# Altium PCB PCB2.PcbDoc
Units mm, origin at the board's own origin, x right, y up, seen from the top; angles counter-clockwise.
Board outline 27.18 x 46.74 mm, 2 copper layers (Top Layer, Bottom Layer); 37 components, 26 nets, 150 pads, 36 vias.
Unrouted connection lines stored in the file: 6.
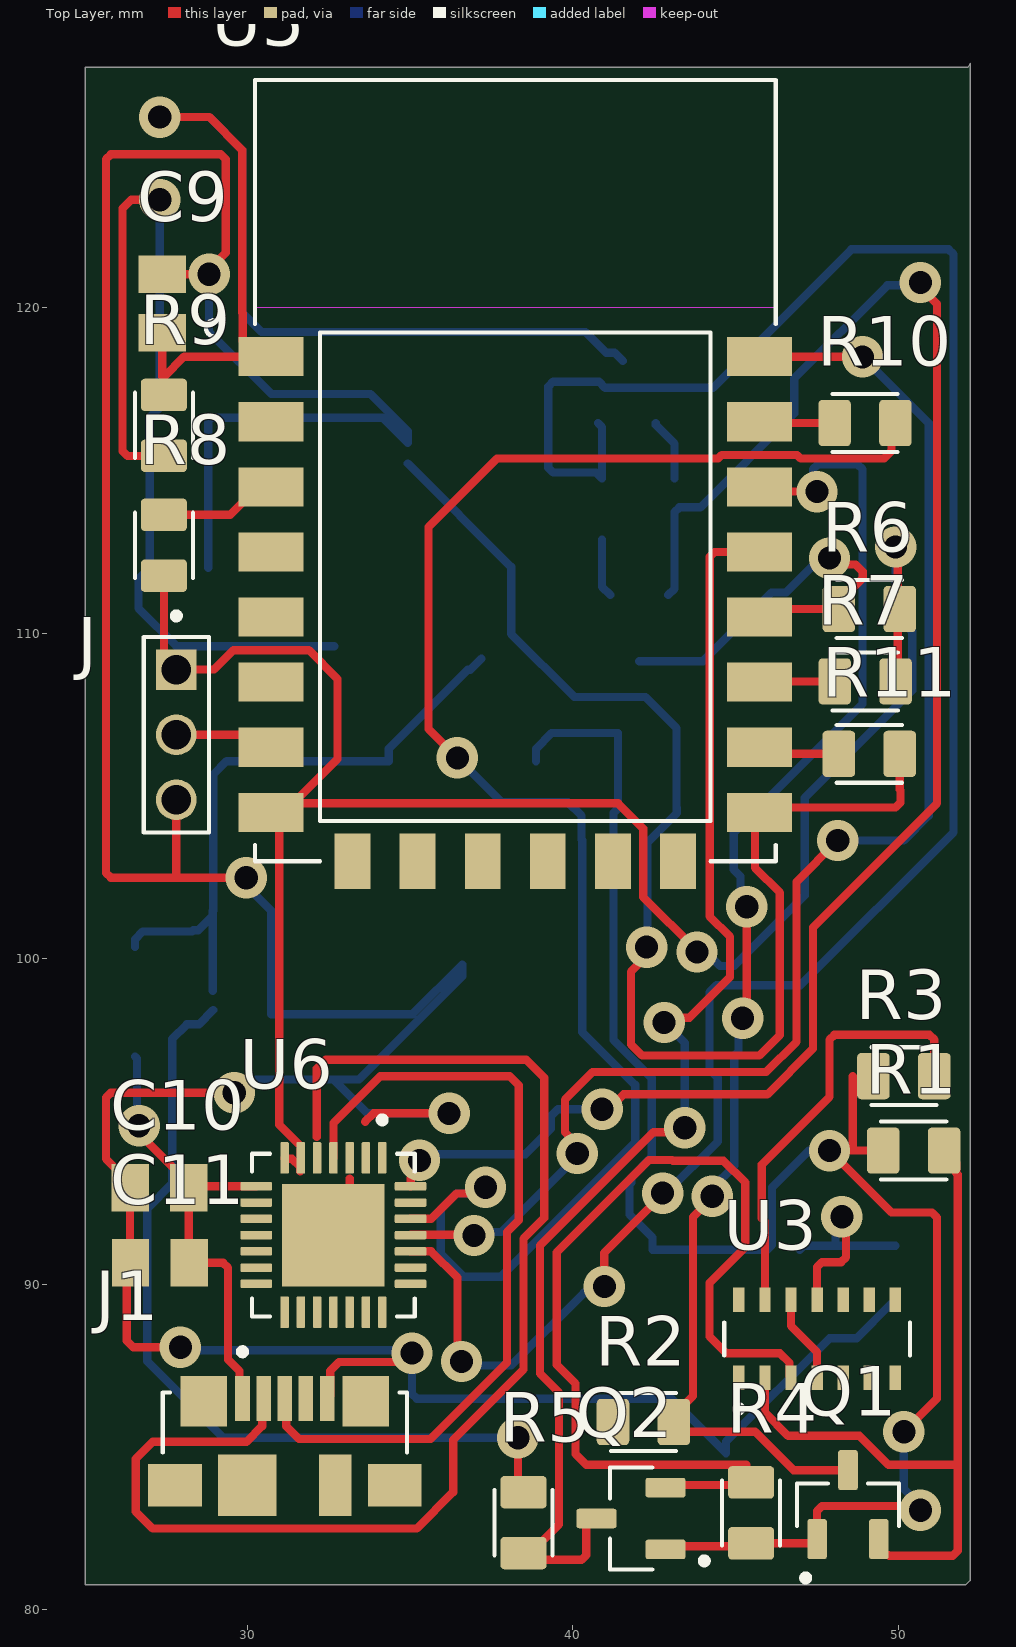
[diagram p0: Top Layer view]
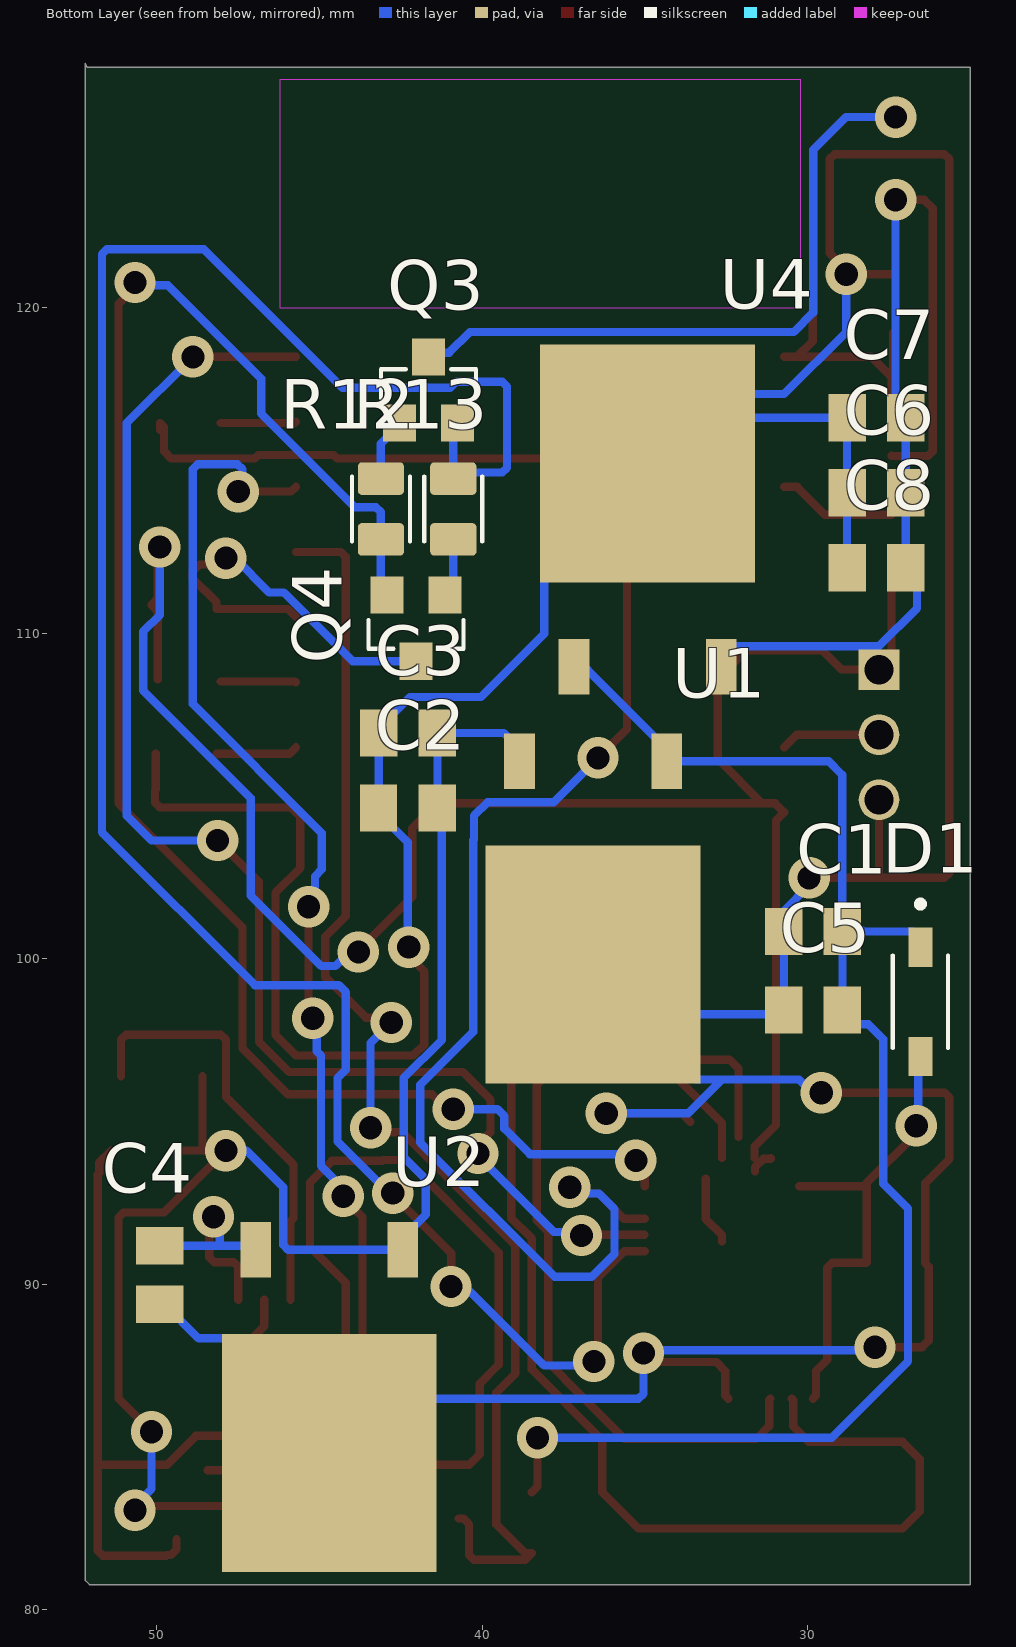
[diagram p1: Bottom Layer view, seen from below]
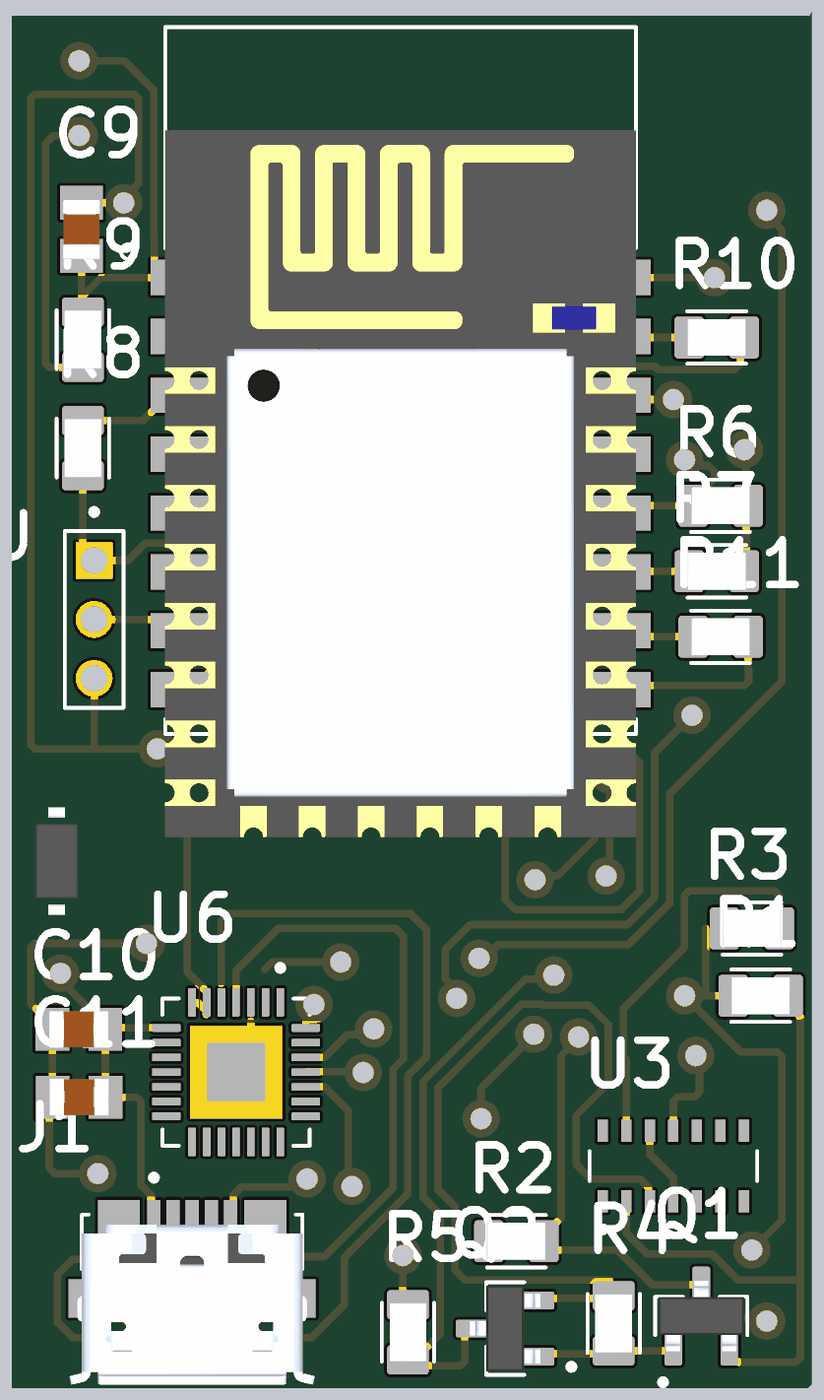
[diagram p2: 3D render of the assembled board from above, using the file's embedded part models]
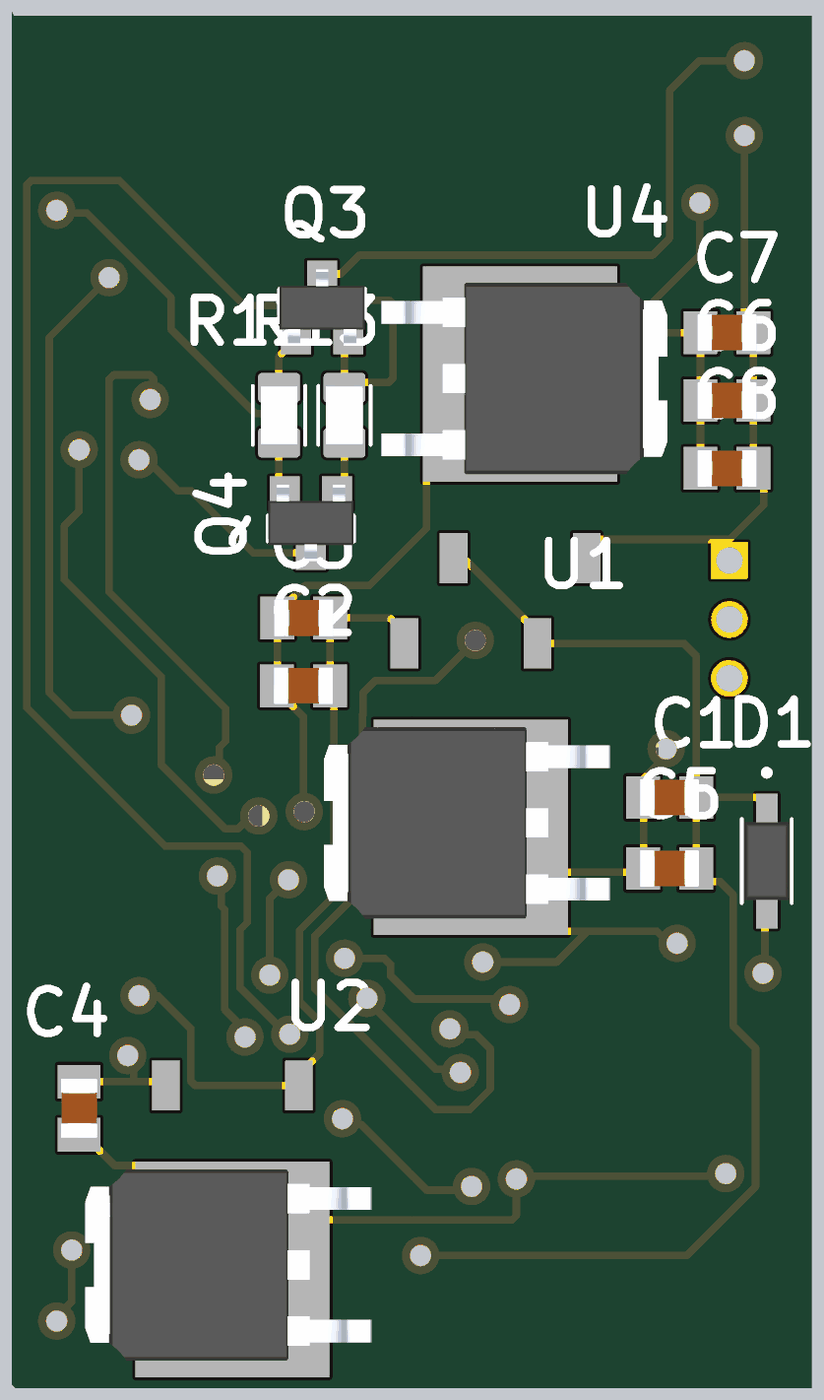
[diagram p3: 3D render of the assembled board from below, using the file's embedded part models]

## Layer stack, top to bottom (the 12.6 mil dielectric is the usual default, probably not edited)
Top Solder: solder mask 0.0102, Solder Resist, Dk 3.5
Top Layer: signal copper 0.0356
Dielectric 1: dielectric 0.32, FR-4, Dk 4.8
Bottom Layer: signal copper 0.0356
Bottom Solder: solder mask 0.0102, Solder Resist, Dk 3.5

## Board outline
25.019,80.772 25.019,127.381 52.133,127.381 52.197,127.508 52.197,80.899 52.07,80.772

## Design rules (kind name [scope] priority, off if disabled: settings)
Clearance [All] p1: gap=0.254 ignorepadtopadclearanceinfootprint=FALSE except(0: Arc-Hole Track-Hole SMDPad-Hole THPad-Hole Via-Hole Fill-Hole Poly-Hole Region-Hole Text-Hole)
HoleToHoleClearance [All] p1 off: gap=0.05 allowstackedmicrovias=TRUE
MinimumSolderMaskSliver [All] p1: minsoldermaskwidth=0.05
PolygonConnect [All] p1: connectstyle=Relief reliefconductorwidth=0.254 reliefentries=4 polygonreliefangle="90 Angle" airgapwidth=0.254
RoutingVias [All] p1: holewidth=0.711 width=1.27 viastyle="Through Hole" minholewidth=0.711 minwidth=1.27 maxholewidth=0.711 maxwidth=1.27
SilkToSilkClearance [All] p1: silktosilkclearance=0.05
SilkToSolderMaskClearance [IsPad] p1: minsilkscreentomaskgap=0.05 clearancetoexposedcopper=TRUE
SolderMaskExpansion [All] p1: expansion=0.102 istentingtop=FALSE
Width [All] p1: maxlimit=0.254 minlimit=0.254 preferedwidth=0.254
26 further rules are at their usual default settings.

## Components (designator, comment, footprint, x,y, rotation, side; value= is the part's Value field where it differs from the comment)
C1 "1uF" CAPC2012X140N 29.845,100.838 r180 bottom
C2 "47uF" CAPC2012X140N 42.291,104.63 r180 bottom
C3 "0.1uF" CAPC2012X140N 42.28,106.934 r180 bottom
C4 "1uF" CAPC2012X140N 49.911,90.286 r90 bottom
C5 "10uF" CAPC2012X140N 29.845,98.425 r180 bottom
C6 "10uF" CAPC2012X140N 27.896,114.318 r180 bottom
C7 "10uF" CAPC2012X140N 27.896,116.623 r0 bottom
C8 "100nF" CAPC2012X140N 27.896,112.014 r0 bottom
C9 "100nF" CAPC2012X140N 27.384,120.131 r270 top
C10 "100nF" CAPC2012X140N 27.294,92.964 r0 top
C11 "10uF" CAPC2012X140N 27.305,90.66 r0 top
D1 "1N5819HW-7-F" SOD3715X145N 26.543,98.679 r270 bottom
J "2355186-3" TE_2355186-3 27.813,108.883 r270 top
J1 "47346-0001" MOLEX_47346-0001 31.145,83.827 r0 top
Q1 "BSS138" SOT95P240X111-3N 48.448,83.229 r90 top
Q2 "BSS138" SOT95P240X111-3N 41.783,82.804 r180 top
Q3 "SMD-TRANSISTORS-NPN-25V-500MW(SOT-23)" SOT-23 41.656,117.475 r180 bottom
Q4 "SMD-TRANSISTORS-NPN-25V-500MW(SOT-23)" SOT-23 42.037,110.158 r0 bottom
R1 "10K" RESC2012X65N 50.465,94.107 r180 top
R2 "10K" RESC2012X65N 42.164,85.768 r180 top
R3 "10K" RESC2012X65N 50.165,96.393 r180 top
R4 "10K" RESC2012X65N 45.472,82.977 r270 top
R5 "10K" RESC2012X65N 38.481,82.677 r90 top
R6 "12K" RESC2012X65N 49.103,110.744 r0 top
R7 "10K" RESC2012X65N 48.976,108.52 r0 top
R8 "10K" RESC2012X65N 27.432,112.702 r270 top
R9 "10K" RESC2012X65N 27.432,116.387 r270 top
R10 "470" RESC2012X65N 48.971,116.459 r0 top
R11 "10K" RESC2012X65N 49.103,106.295 r0 top
R12 "12K" RESC2012X65N 43.118,113.817 r90 bottom
R13 "12K" RESC2012X65N 40.894,113.817 r270 bottom
U1 "LF33CDT-TR" TO228P972X240-3N 36.599,99.974 r0 bottom
U2 "LF33CDT-TR" TO228P972X240-3N 44.704,84.963 r0 bottom
U3 "MAX30102EFD+T" XDCR_MAX30101EFD+ 47.498,88.322 r90 top
U4 "LF33CDT-TR" TO228P972X240-3N 34.925,115.062 r180 bottom
U5 "ESP8266-12E/ESP-12E" XCVR_ESP8266-12E/ESP-12E 38.227,111.497 r0 top
U6 "CP2102" QFN50P500X500X100-29N 32.639,91.511 r270 top

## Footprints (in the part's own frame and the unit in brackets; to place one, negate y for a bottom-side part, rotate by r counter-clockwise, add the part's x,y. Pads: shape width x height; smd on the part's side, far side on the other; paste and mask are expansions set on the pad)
CAPC2012X140N [mm]
  rect 1.15x1.45 smd: 1(-0.9,0) 2(0.9,0)
  body extent -1,-0.63 1,0.63, height 0.94
MOLEX_47346-0001 [mm]
  rect 0.45x1.38 smd: 1(-1.3,2.66) 2(-0.65,2.66) 3(0,2.66) 4(0.65,2.66) 5(1.3,2.66)
  rect 1.425x1.55 smd: S1(-2.488,2.575) S2(2.488,2.575)
  rect 1.65x1.3 smd: S3(-3.375,0) S6(3.375,0)
  rect 1.8x1.9 smd: S4(-1.15,0)
  rect 1x1.9 smd: S5(1.55,0)
  silkscreen extent -3.75,1 3.75,4.2, body extent -4.18,-2.93 4.18,2.5, height 2.7
QFN50P500X500X100-29N [mm]
  rrect25% 0.97x0.26 smd: 1(-2.37,1.5) 2(-2.37,1) 3(-2.37,0.5) 4(-2.37,0) 5(-2.37,-0.5) 6(-2.37,-1) 7(-2.37,-1.5) 15(2.37,-1.5) 16(2.37,-1) 17(2.37,-0.5) 18(2.37,0) 19(2.37,0.5) 20(2.37,1) 21(2.37,1.5)
  rrect25% 0.26x0.97 smd: 8(-1.5,-2.37) 9(-1,-2.37) 10(-0.5,-2.37) 11(0,-2.37) 12(0.5,-2.37) 13(1,-2.37) 14(1.5,-2.37) 22(1.5,2.37) 23(1,2.37) 24(0.5,2.37) 25(0,2.37) 26(-0.5,2.37) 27(-1,2.37) 28(-1.5,2.37)
  rect 3.15x3.15 smd paste-0.575: 29(0,0)
  silkscreen extent -3.64,-2.5 2.5,2.5
RESC2012X65N [mm]
  rrect25% 1x1.42 smd: 1(-0.935,0) 2(0.935,0)
  silkscreen extent -1,-0.89 1,0.89, body extent -1,-0.63 1,0.63, height 0.6
SOD3715X145N [mm]
  rect 1.21x0.73 smd: A(1.68,0) C(-1.68,0)
  silkscreen extent -3.1,-0.85 1.42,0.85, body extent -1.83,-0.77 1.83,0.77, height 0.8
SOT95P240X111-3N [mm]
  rrect25% 1.23x0.6 smd: 1(-1.06,0.95) 2(-1.06,-0.95) 3(1.06,0)
  silkscreen extent -2.35,-1.57 0.65,1.57, body extent -1.2,-1.46 1.2,1.46, height 1.2
SOT-23 [mil]
  rect 40x45 smd: 1(-35,-40) 2(35,-40) 3(0,40)
  silkscreen extent -58,-10 58,25, body extent -57,-51 57,51, height 55
TE_2355186-3 [mm]
  rect 1.25x1.25 hole 0.9: 1(0,0)
  round 1.25 hole 0.9: 2(2,0) 3(4,0)
  silkscreen extent -1.75,-1 5,1
TO228P972X240-3N [mil]
  rect 37x67 smd: 1(-89,-240) 3(89,-240)
  rect 260x288 smd: 2(0,6)
  body extent -186,-128 197,128, height 94
XCVR_ESP8266-12E/ESP-12E [mm]
  rect 2x1.2 smd: 1(-7.5,7) 2(-7.5,5) 3(-7.5,3) 4(-7.5,1) 5(-7.5,-1) 6(-7.5,-3) 7(-7.5,-5) 8(-7.5,-7) 15(7.5,-7) 16(7.5,-5) 17(7.5,-3) 18(7.5,-1) 19(7.5,1) 20(7.5,3) 21(7.5,5) 22(7.5,7)
  rect 1.1x1.7 smd: 9(-5,-8.5) 10(-3,-8.5) 11(-1,-8.5) 12(1,-8.5) 13(3,-8.5) 14(5,-8.5)
  Keep-Out Layer region: 8,8.51 -8.009,8.51 -8.009,15.5 8,15.5
  Keep-Out Layer region: 8,8.51 -8.009,8.51 -8.009,15.5 8,15.5
  silkscreen extent -9.5,-8.5 8,15.5, body extent -8,-12 8,12, height 3
XDCR_MAX30101EFD+ [mm]
  rect 0.75x0.35 smd: 1(-1.2,2.4) 2(-1.2,1.6) 3(-1.2,0.8) 4(-1.2,0) 5(-1.2,-0.8) 6(-1.2,-1.6) 7(-1.2,-2.4) 8(1.2,-2.4) 9(1.2,-1.6) 10(1.2,-0.8) 11(1.2,0) 12(1.2,0.8) 13(1.2,1.6) 14(1.2,2.4)
  silkscreen extent -2.25,-2.85 0.51,2.85

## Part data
C1 C2 C3 C4 C5 C6 C7 C8 C9 C10 C11: library part LD051C121KAB2A, "Ceramic Capacitor", Package="0805 AVX"
D1: "Diode Schottky 40 V 1A Surface Mount SOD-123", Package="SOD-123 Fairchild Semiconductor"
J: "Pin 3P,2MM,BRK HDR,SRVT,2.8,0.76AU,BOX 3 POS", Package=None
J1: "USB - micro B USB 2.0 Receptacle Connector 5 Position Surface Mount, Right Angle", Package=None
Q1 Q2: "N-Channel 50 V 220mA (Ta) 350mW (Ta) Surface Mount SOT-23-3", Package="SOT-23-3 Motorola"
Q3 Q4: "Bipolar (BJT) Transistor NPN 25 V 500 mA 150MHz 300 mW Surface Mount SOT-23", Package=None
R1 R2 R3 R4 R5 R6 R7 R8 R9 R10 R11 R12 R13: library part 2-2176053-0, "RES 0.33 OHM 1% 1/4W 0805", Package=0805, Power_Rating=".25 W", Resistance=.33, Tolerance=1%
U1 U2 U4: "Linear Voltage Regulator IC Positive Fixed 1 Output 500mA DPAK", Package="TO-252-3 STMicroelectronics"
U3: "Pulse Oximeter and Heart Rate Sensor Digital Output", Package=None
U5: "This WiFi module has a 32-bit MCU micro and clock speeds supporting 80 MHz or 160 MHz. Supports the RTOS and integrated Wi-Fi MAC/BB/RF/PA/LNA, and has an on-board antenna.", Package=None
U6: "CP2102N USB 2.0 to UART (RS232) Bridge Interface Evaluation Board", Package="WFQFN-20 Silicon Labs"

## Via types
v1: diameter 1.27, hole 0.711, Top Layer to Bottom Layer, tented both sides, 36 vias

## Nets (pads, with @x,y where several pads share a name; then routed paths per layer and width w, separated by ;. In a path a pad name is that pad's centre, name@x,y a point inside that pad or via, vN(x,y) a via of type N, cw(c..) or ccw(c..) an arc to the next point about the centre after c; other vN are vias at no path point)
1V8: C4.2 U2.3 U3.11 | length 7.3
  Top Layer w0.254: U3.11 47.498,90.529 47.647,90.678 48.238,90.678 48.387,90.827 48.387,91.948 v1(48.26,92.075)
  Bottom Layer w0.254: U2.3 47.092,91.186 48.006,91.186 ; v1(48.26,92.075) 48.066,91.881 48.066,91.246 48.006,91.186 ; C4.2 48.006,91.186
3V3: C2.2 C3.2 Q1.1 Q2.1 R1.2 R3.2 R4.2 U1.3 U2.1 | length 54.5
  Top Layer w0.254: Q2.1 42.937,81.948 45.378,81.948 R4.2 47.371,82.042 Q1.1 47.498,83.036 47.647,83.185 50.546,83.185 v1(50.673,83.058) ; 48.595,96.393 48.595,94.107 ; R1.2 48.595,94.107 ; v1(50.165,85.471) 51.181,86.487 51.181,92.053 51.032,92.202 49.784,92.202 v1(47.879,94.107) 48.595,94.107
  Bottom Layer w0.254: U1.3 38.86,106.451 39.342,106.934 C3.2 41.38,104.641 C2.2 41.246,104.485 41.246,97.508 42.418,96.336 42.418,93.907 41.791,93.281 41.791,93.121 41.739,93.069 41.739,92.144 42.443,91.44 U2.1 45.965,91.059 46.114,91.208 46.114,92.977 47.244,94.107 v1(47.879,94.107) ; v1(50.165,85.471) 50.165,83.715 50.673,83.207 v1(50.673,83.058)
3V3_ESP: C6.2 C7.1 C8.1 J.1 R6.2 R7.2 R8.2 R9.2 U4.3 U5.8 U6.6 U6.7 | length 91.4
  Top Layer w0.254: v1(27.305,123.317) 26.426,123.317 26.162,123.053 26.162,115.592 26.311,115.443 27.423,115.443 R9.2 ; R8.2 27.432,109.264 J.1 28.974,108.883 29.569,109.478 31.885,109.478 32.766,108.597 32.766,106.136 U5.8@31.405,104.775 ; U6.7 31.139,93.856 31.142,93.853 31.369,93.853 31.623,93.599 U6.6@31.623,93.467 ; U6.6 31.639,94.236 30.977,94.898 30.977,104.247 U5.8 31.005,104.775 U5.8@31.405,104.775 ; v1(43.808,100.21) 43.808,100.248 42.158,101.898 42.158,104.005 41.388,104.775 U5.8@31.405,104.775 ; v1(49.911,112.649) 49.974,112.585 49.974,111.061 50.165,110.871 49.974,110.68 R7.2@49.974,108.583
  Bottom Layer w0.254: v1(27.305,123.317) 27.305,116.932 C7.1 C6.2 C8.1 26.648,111.666 26.648,110.766 27.813,109.601 U4.3@32.664,109.601 ; v1(43.808,100.21) 44.083,100.21 44.518,99.775 44.951,99.775 47.117,101.941 47.117,104.941 50.419,108.243 50.419,110.055 49.911,110.563 v1(49.911,112.649)
ASCL: Q1.3 R2.1 U5.20 | length 42.2
  Top Layer w0.254: v1(44.276,92.705) 44.276,92.66 43.686,92.069 43.686,86.565 43.099,85.978 R2.1 43.396,85.471 45.589,85.471 46.771,84.289 Q1.3 ; v1(45.212,98.171) 45.339,98.298 v1(45.339,101.6) ; U5.20 45.872,114.352 v1(47.498,114.352)
  Bottom Layer w0.254: v1(44.276,92.705) 44.276,92.958 44.958,93.64 44.958,97.028 45.085,97.155 45.085,98.044 v1(45.212,98.171) ; v1(45.339,101.6) 45.145,101.794 45.145,102.535 44.936,102.743 44.936,103.864 48.895,107.823 48.895,115.04 48.746,115.189 47.52,115.189 47.371,115.04 47.371,114.479 v1(47.498,114.352)
ASDA: Q2.3 R5.1 U5.19 | length 40.5
  Top Layer w0.254: Q2.3 40.581,82.804 40.408,82.631 40.408,81.683 40.259,81.534 38.689,81.534 R5.1 38.691,81.742 39.572,82.623 39.572,86.675 38.989,87.258 38.989,91.188 42.472,94.671 43.298,94.671 v1(43.434,94.807) ; v1(42.799,98.044) 42.946,98.191 43.581,98.191 44.824,99.434 44.824,100.678 44.199,101.303 44.199,112.348 44.348,112.497 U5.19
  Bottom Layer w0.254: v1(42.799,98.044) 43.434,97.409 v1(43.434,94.807)
AVCC: C1.2 C5.2 D1.C R2.2 R5.2 U1.1 U4.1 | length 45.5
  Top Layer w0.254: v1(38.307,85.284) 38.307,83.786 R5.2
  Bottom Layer w0.254: D1.C 26.543,100.599 26.781,100.837 26.929,100.837 26.93,100.838 28.299,100.838 28.336,100.875 28.486,100.875 C1.2@28.934,101.323 ; C5.2@28.934,99.019 C1.2@28.934,101.323 ; C1.2@28.934,101.473 C1.2@28.934,101.323 ; C5.2 28.508,97.988 28.138,97.988 27.686,97.536 27.686,93.09 26.923,92.326 26.923,87.631 29.27,85.284 v1(38.307,85.284) ; C1.2@28.945,101.473 28.945,105.653 29.362,106.07 U1.1 34.339,106.451 36.764,108.877 36.843,108.877 U4.1@37.186,109.22
BSCL: Q1.2 R1.1 U3.2 | length 23
  Top Layer w0.254: U3.2 45.898,86.055 46.609,85.344 48.803,85.344 49.692,84.455 51.816,84.455 ; Q1.2 49.398,81.854 49.571,81.681 49.7,81.681 49.72,81.661 51.667,81.661 51.816,81.81 51.816,84.455 ; R1.1 51.773,93.734 51.773,93.418 51.816,93.375 51.816,84.455
BSDA: Q2.2 R4.1 U3.3 | length 30.8
  Top Layer w0.254: Q2.2 42.922,83.833 45.393,83.833 R4.1 45.323,84.061 45.323,84.455 40.408,84.455 40.08,84.783 40.08,86.949 39.497,87.532 39.497,90.978 42.334,93.815 43.05,93.815 43.074,93.791 44.627,93.791 45.292,93.126 45.292,91.139 44.196,90.043 44.196,88.392 44.71,87.878 46.361,87.878 46.65,87.589 46.65,87.17 U3.3
D_N: J1.2 U6.5 | length 40.5
  Top Layer w0.254: J1.2 30.451,86.443 30.451,85.639 29.97,85.158 27.087,85.158 26.564,84.635 26.564,83.019 27.087,82.496 35.203,82.496 36.318,83.611 36.318,85.217 38.481,87.38 38.481,91.399 39.116,92.034 39.116,96.347 38.562,96.901 32.407,96.901 32.131,96.625 32.131,94.524
D_P: J1.3 U6.4 | length 24.9
  Top Layer w0.254: J1.3 31.189,86.443 31.189,85.639 31.582,85.246 35.629,85.246 36.996,86.613 37.973,87.59 37.973,91.609 38.33,91.966 38.33,96.117 38.054,96.393 34.08,96.393 32.639,94.952 32.639,94.516 U6.4
DTR: Q4.2 R12.1 U6.28 | length 53.7
  Top Layer w0.254: U6.28 35.012,93.014 35.012,93.26 35.284,93.532 v1(35.284,93.807) ; v1(40.894,95.377) 41.091,95.377 41.551,95.837 45.97,95.837 47.371,97.238 47.371,100.965 51.181,104.775 51.181,120.12 50.673,120.628 v1(50.673,120.777)
  Bottom Layer w0.254: v1(35.284,93.807) 35.472,93.996 38.544,93.996 39.328,94.779 39.328,95.165 39.539,95.377 v1(40.894,95.377) ; Q4.2 43.118,111.367 R12.1 43.118,113.722 43.267,113.871 43.913,113.871 46.795,116.753 46.795,117.828 49.657,120.69 50.586,120.69 v1(50.673,120.777)
EN: R8.1 U5.3 | length 3.7
  Top Layer w0.254: R8.1 29.467,113.637 30.327,114.497 U5.3
GND: C1.1 C2.1 C3.1 C4.1 C5.1 C6.1 C7.2 C8.2 C9.1 C10.1 C11.1 J1.5 J.3 R11.2 U1.2 U2.2 U3.4 U3.12 U4.2 U5.15 U6.3 U6.29 | length 174.2
  Top Layer w0.254: 26.924,102.489 25.803,102.489 25.654,102.638 25.654,124.565 25.803,124.714 29.18,124.714 29.329,124.565 29.329,121.688 28.821,121.18 v1(28.821,121.031) C9.1 ; 26.949,102.489 27.813,102.489 ; J.3 27.813,102.489 ; v1(27.939,88.066) 26.488,88.066 26.289,88.265 26.289,90.544 C11.1 26.394,90.671 C10.1 26.394,93.114 25.654,93.854 25.654,95.736 25.803,95.885 v1(29.591,95.885) ; v1(29.961,102.489) 27.813,102.489 ; J1.5 32.539,86.581 32.539,87.335 32.814,87.609 34.777,87.609 v1(35.052,87.884) ; U6.29@32.639,91.313 U6.29 33.139,92.011 33.139,93.246 ; 33.614,94.996 33.868,95.25 v1(36.195,95.25) ; v1(42.262,100.357) 42.262,100.082 41.783,99.603 41.783,97.369 42.124,97.028 45.724,97.028 46.355,97.659 46.355,102.03 45.593,102.792 45.593,104.363 U5.15 45.878,104.648 49.911,104.648 50.06,104.797 50.06,105.18 50.038,105.202 R11.2 ; U3.12 46.698,88.722 47.498,87.922 U3.4
  Bottom Layer w0.254: v1(27.939,88.066) 28.03,87.975 34.961,87.975 v1(35.052,87.884) 35.052,86.636 35.201,86.487 43.028,86.487 U2.2 44.704,85.166 47.879,88.341 48.716,88.341 49.761,89.386 C4.1 ; C8.2 C6.1 C7.2 34.152,116.623 34.925,115.849 34.925,116.205 33.782,117.348 30.734,117.348 28.821,119.261 v1(28.821,121.031) ; v1(29.591,95.885) 29.866,95.885 30.272,96.291 32.639,96.291 ; v1(29.961,102.489) 29.961,102.246 C1.1@30.734,101.473 ; C1.1@30.734,101.462 30.734,100.838 30.734,98.298 35.075,98.298 U1.2 36.599,99.466 33.424,96.291 32.639,96.291 ; U4.2 38.1,112.039 38.1,109.982 40.042,108.04 42.224,108.04 43.18,107.084 C3.1 43.18,104.641 C2.1 43.191,104.48 42.289,103.578 42.289,100.384 v1(42.262,100.357) ; v1(36.195,95.25) 33.68,95.25 32.639,96.291
GPIO0: Q4.3 R6.1 U5.18 | length 12.3
  Top Layer w0.254: U5.18 45.974,110.744 R6.1 48.168,110.954 48.9,111.686 48.9,111.897 48.684,112.112 48.073,112.112 v1(47.879,112.307)
  Bottom Layer w0.254: Q4.3 43.991,109.142 46.101,111.252 46.549,111.252 47.604,112.307 v1(47.879,112.307)
GPIO2: R7.1 U5.17 | length 2.3
  Top Layer w0.254: U5.17 45.75,108.52 R7.1
GPIO13: J.2 U5.7 | length 3.1
  Top Layer w0.254: J.2 30.341,106.883 U5.7
GPIO15: R11.1 U5.16 | length 2.5
  Top Layer w0.254: U5.16 45.929,106.295 R11.1
INT: R3.1 U3.13 | length 13.4
  Top Layer w0.254: U3.13 45.898,91.933 45.8,92.031 45.8,93.679 47.879,95.758 47.879,97.514 48.028,97.663 50.951,97.663 51.1,97.514 51.1,96.625 R3.1
NetQ3_1: Q3.1 R12.2 | length 1.9
  Bottom Layer w0.254: Q3.1 42.545,116.395 43.118,115.822 R12.2
NetQ4_1: Q4.1 R13.2 | length 1.8
  Bottom Layer w0.254: R13.2 40.894,111.428 Q4.1
NetR10_2: R10.2 U6.26 | length 52.8
  Top Layer w0.254: U6.26 35.644,92.011 36.418,92.785 37.119,92.785 v1(37.314,92.98) ; v1(36.449,106.172) 35.56,107.061 35.56,113.262 37.666,115.368 44.459,115.368 44.569,115.478 46.885,115.478 46.995,115.368 49.56,115.368 49.784,115.592 49.784,116.337 R10.2 R10.2@49.906,116.249
  Bottom Layer w0.254: v1(36.449,106.172) 37.813,104.808 39.845,104.808 40.259,104.394 40.259,103.661 40.282,103.637 40.282,97.753 41.91,96.125 41.91,94.358 37.785,90.233 36.639,90.233 35.941,90.932 35.941,92.308 36.418,92.785 37.119,92.785 v1(37.314,92.98)
nRST: C9.2 Q3.3 R9.1 U5.1 | length 35.2
  Top Layer w0.254: v1(27.305,125.857) 28.829,125.857 29.837,124.849 29.837,119.849 29.854,119.832 29.854,118.97 30.327,118.497 28.055,118.497 27.432,117.874 R9.1 ; 27.384,117.874 C9.2 ; U5.1@30.357,118.497 U5.1
  Bottom Layer w0.254: v1(27.305,125.857) 28.829,125.857 29.837,124.849 29.837,119.849 30.433,119.253 40.386,119.253 41.021,118.618 41.275,118.618 Q3.3@41.529,118.364
RTS: Q3.2 R13.1 U6.24 | length 68.2
  Top Layer w0.254: U6.24 35.644,91.011 36.449,90.206 36.449,87.755 v1(36.575,87.629) ; v1(40.964,89.93) 40.96,89.934 40.96,90.958 42.755,92.753 v1(42.755,92.799)
  Bottom Layer w0.254: v1(36.575,87.629) 36.701,87.503 38.1,87.503 40.333,89.736 40.769,89.736 v1(40.964,89.93) ; Q3.2 40.894,116.332 R13.1 40.711,114.935 39.392,114.935 39.243,115.084 39.243,117.58 39.392,117.729 40.8,117.729 40.99,117.538 44.298,117.538 48.552,121.793 51.54,121.793 51.689,121.644 51.689,103.886 46.99,99.187 44.41,99.187 44.196,98.973 44.196,96.593 44.45,96.339 44.45,94.386 42.863,92.799 v1(42.755,92.799)
RXD: R10.1 U5.21 | length 2.3
  Top Layer w0.254: U5.21 45.765,116.459 R10.1
TXD: U5.22 U6.25 | length 43.8
  Top Layer w0.254: U6.25@35.02,91.522 36.933,91.522 v1(36.957,91.498) ; 39.808,94.616 40.132,94.292 v1(40.132,94.017) ; 39.808,94.617 39.751,94.674 39.751,95.671 40.6,96.52 45.934,96.52 46.863,97.449 46.863,102.362 v1(48.133,103.632) ; U5.22 48.889,118.497 v1(48.895,118.491)
  Bottom Layer w0.254: v1(36.957,91.498) 37.068,91.609 37.799,91.609 40.132,93.942 v1(40.132,94.017) ; v1(48.133,103.632) 50.165,103.632 50.927,104.394 50.927,116.459 v1(48.895,118.491)
VDDUSB: C10.2 C11.2 D1.A J1.1 U6.8 | length 14.6
  Top Layer w0.254: v1(26.67,94.869) 26.67,94.638 28.194,93.114 C10.2 ; C11.2@28.194,90.671 C10.2 ; C11.2 29.254,90.66 29.403,90.511 29.403,87.683 29.751,87.335 29.751,86.581 J1.1 ; U6.8 28.241,93.011 C10.2
  Bottom Layer w0.254: D1.A 26.607,96.936 26.607,94.932 v1(26.67,94.869)
pads on no net: J1.4 J1.S1 J1.S2 J1.S3 J1.S4 J1.S5 J1.S6 U3.1 U3.5 U3.6 U3.7 U3.8 U3.9 U3.10 U3.14 U5.2 U5.4 U5.5 U5.6 U5.9 U5.10 U5.11 U5.12 U5.13 U5.14 U6.1 U6.2 U6.9 U6.10 U6.11 U6.12 U6.13 U6.14 U6.15 U6.16 U6.17 U6.18 U6.19 U6.20 U6.21 U6.22 U6.23 U6.27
